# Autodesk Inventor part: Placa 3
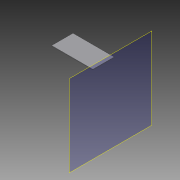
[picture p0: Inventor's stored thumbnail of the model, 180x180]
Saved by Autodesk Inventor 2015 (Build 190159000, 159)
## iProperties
Created: 2015-04
Part Number: Placa 3
Material: Generic
Document SubType Name: Modeling
Designer: suporte
Density: 1 g/cm^3
Appearance: Default
Author: suporte
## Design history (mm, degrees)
workplane "Work Plane1"
sketch "Sketch1"
  geometry: L1 (-175.237, 886.9)-(566.84, 886.9) reference; L2 (430.862, 887.5)-(-87.737, 887.5); L3 (-87.737, 887.5)-(-87.737, 900); L4 (-87.737, 900)-(430.862, 900); L5 (430.862, 900)-(430.862, 887.5); 2 further points
  constraints: 8 end point, 2 parallel, 1 coincident, 1 horizontal, 1 perpendicular, 2 other
  dimensions: "d0" = 12.5 distance of L2.end L3.end
extrude "Extrusion1" new body sketch "Sketch1" distance "d1" = 1000; taper "d2" = 0 deg
body "Solid1"
node "Reference1"
